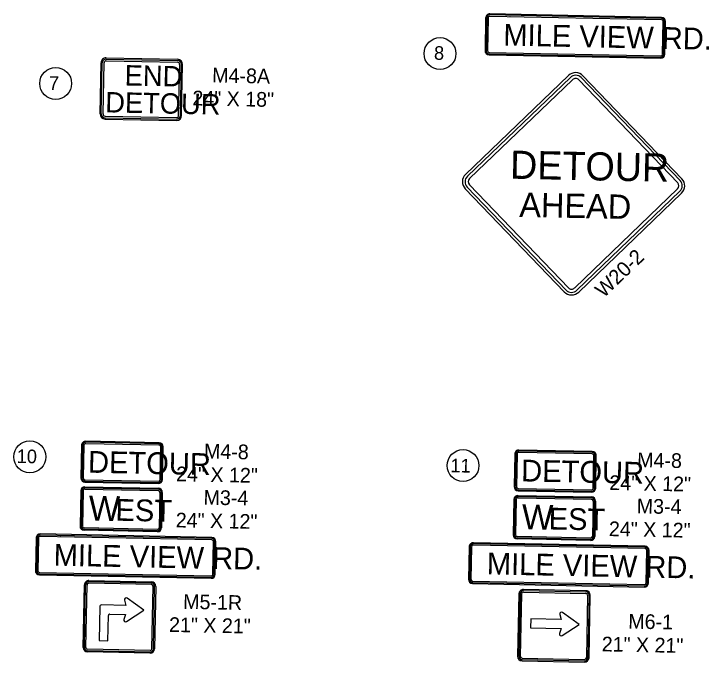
# Model space of a CAD drawing. Extents: x 299354 to 1325680, y 96128 to 228242.
# Drawn here: x 1320252 to 1322808, y 149023 to 151405 of the extents above; entities that cross this region are included whole.
import ezdxf

# ---------------------------------------------------------------- set-up
doc = ezdxf.new("R2010")
doc.units = 0
doc.layers.add('CA-TEXT', color=7, linetype='Continuous')
doc.layers.add('P_SGN_Cell', color=7, linetype='Continuous')

msp = doc.modelspace()

# ---------------------------------------------------------------- linework, layer by layer
at = {"layer": 'CA-TEXT'}
for centre in [(1321818.8, 151259.5), (1320405.8, 151149.7), (1320311, 149777), (1321903.4, 149745)]:
    msp.add_circle(centre, 58.6, dxfattribs=at)
at = {"layer": 'P_SGN_Cell'}
for p, q in [((1320591.9, 151243.8), (1320854.3, 151238.5)), ((1320569, 151038), (1320572.7, 151225.4)), ((1320573.7, 151037.9), (1320577.4, 151225.3)), ((1320579.9, 151037.8), (1320583.7, 151225.2)), ((1320591.7, 151232.9), (1320854.1, 151227.6)), ((1320591.8, 151239.1), (1320854.2, 151233.8)), ((1320858, 151032.2), (1320861.8, 151219.6)), ((1320864.2, 151032), (1320868, 151219.5)), ((1320868.9, 151031.9), (1320872.7, 151219.4)), ((1320587.3, 151018.9), (1320849.8, 151013.6)), ((1320587.4, 151023.5), (1320849.9, 151018.3)), ((1320587.6, 151029.8), (1320850, 151024.5)), ((1320513.1, 149667.2), (1320783.2, 149661.7)), ((1320513.1, 149658.4), (1320783, 149653)), ((1320513.2, 149663.4), (1320783.1, 149658)), ((1320498, 149652.5), (1320495.4, 149522.5)), ((1320501.7, 149652.4), (1320499.1, 149522.4)), ((1320506.7, 149652.3), (1320504.1, 149522.3)), ((1320789.2, 149646.6), (1320786.5, 149516.6)), ((1320794.2, 149646.5), (1320791.5, 149516.5)), ((1320797.9, 149646.4), (1320795.3, 149516.4)), ((1322105.5, 149635.1), (1322375.6, 149629.6)), ((1322105.6, 149631.3), (1322375.5, 149625.9)), ((1322090.4, 149620.4), (1322087.7, 149490.4)), ((1322094.1, 149620.3), (1322091.5, 149490.3)), ((1322099.1, 149620.2), (1322096.5, 149490.2)), ((1322105.5, 149626.3), (1322375.4, 149620.9)), ((1322381.5, 149614.5), (1322378.9, 149484.5)), ((1322386.5, 149614.4), (1322383.9, 149484.4)), ((1322390.3, 149614.3), (1322387.7, 149484.4)), ((1320780, 149501.7), (1320510, 149507.2)), ((1320780.1, 149505.5), (1320510.1, 149510.9)), ((1320780.2, 149510.5), (1320510.2, 149515.9)), ((1322372.4, 149473.4), (1322102.5, 149478.9)), ((1322372.6, 149478.4), (1322102.6, 149483.9)), ((1322372.4, 149469.7), (1322102.4, 149475.1)), ((1320506.9, 149076.5), (1320511.5, 149306.2)), ((1320511.3, 149076.4), (1320515.9, 149306.1)), ((1320516.8, 149076.3), (1320521.4, 149306)), ((1320757.7, 149307.8), (1320528.1, 149312.4)), ((1320757.8, 149313.2), (1320528.2, 149317.9)), ((1320528.3, 149322.2), (1320757.9, 149317.6)), ((1320759.5, 149071.4), (1320764.1, 149301.1)), ((1320765, 149071.3), (1320769.6, 149301)), ((1320774, 149300.9), (1320769.4, 149071.2)), ((1322108.8, 149273.5), (1322104.2, 149043.9)), ((1322113.2, 149273.4), (1322108.6, 149043.8)), ((1322118.6, 149273.3), (1322114, 149043.7)), ((1322125.3, 149279.7), (1322355, 149275.1)), ((1322355.2, 149285), (1322125.5, 149289.6)), ((1322125.5, 149285.2), (1322355.1, 149280.6)), ((1320658.4, 149249.9), (1320663.7, 149230.9)), ((1320729.5, 149213.2), (1320668.5, 149257)), ((1322361.4, 149268.4), (1322356.8, 149038.8)), ((1322366.9, 149268.3), (1322362.3, 149038.7)), ((1322366.6, 149038.6), (1322371.3, 149268.2)), ((1320567.9, 149226.3), (1320565.4, 149101.6)), ((1320663.7, 149230.9), (1320574.6, 149232.7)), ((1320605.6, 149199.2), (1320663, 149198.1)), ((1320663, 149198.1), (1320656.9, 149179.3)), ((1320666.8, 149171.8), (1320729.5, 149213.2)), ((1322259.3, 149197.9), (1322264.6, 149178.9)), ((1322330.4, 149161.1), (1322269.4, 149205)), ((1320598.2, 149100.9), (1320600.1, 149193.9)), ((1322152.5, 149181.1), (1322151.9, 149148.3)), ((1322264.6, 149178.9), (1322152.5, 149181.1)), ((1322151.9, 149148.3), (1322263.9, 149146.1)), ((1322263.9, 149146.1), (1322257.8, 149127.3)), ((1322267.7, 149119.8), (1322330.4, 149161.1)), ((1320565.4, 149101.6), (1320598.2, 149100.9)), ((1320752.8, 149065), (1320523.2, 149069.6)), ((1320752.6, 149055.2), (1320523, 149059.8)), ((1320752.7, 149059.5), (1320523.1, 149064.2)), ((1322120.3, 149031.5), (1322350, 149026.9)), ((1322120.3, 149027.1), (1322349.9, 149022.5)), ((1322120.5, 149037), (1322350.1, 149032.4))]:
    msp.add_line(p, q, dxfattribs=at)
for points in [[(1322633.1, 151383.7), (1322001.7, 151396.4)], [(1322633.2, 151388.7), (1322001.8, 151401.4)], [(1322633.3, 151392.5), (1322001.9, 151405.4)], [(1321986.6, 151390.5), (1321984.2, 151270.5)], [(1321990.4, 151390.4), (1321987.9, 151270.4)], [(1321995.4, 151390.3), (1321992.9, 151270.3)], [(1322636.8, 151257.4), (1322639.2, 151377.4)], [(1322641.8, 151257.3), (1322644.2, 151377.3)], [(1322645.6, 151257.2), (1322648, 151377.2)], [(1321998.9, 151255.2), (1322631, 151242.5)], [(1321999, 151259), (1322630.3, 151246.3)], [(1321999.1, 151264), (1322630.4, 151251.3)], [(1322291.3, 151179.1), (1321912.7, 150815.4)], [(1322297.9, 151172.2), (1321919.3, 150808.5)], [(1322701.2, 150792.8), (1322337.5, 151171.4)], [(1322708, 150799.4), (1322344.4, 151178)], [(1322306.2, 151163.6), (1321927.6, 150799.9)], [(1322692.6, 150784.5), (1322328.9, 151163.2)], [(1321911.6, 150762.4), (1322275.3, 150383.8)], [(1321918.5, 150769), (1322282.2, 150390.3)], [(1321927.1, 150777.2), (1322290.8, 150398.6)], [(1322313.8, 150398.4), (1322692.3, 150762)], [(1322322.1, 150389.8), (1322700.6, 150753.4)], [(1322328.7, 150383), (1322707.1, 150746.5)], [(1320501.1, 149819.6), (1320498.7, 149699.6)], [(1320504.8, 149819.5), (1320502.4, 149699.5)], [(1320509.8, 149819.4), (1320507.4, 149699.4)], [(1320786.2, 149820.1), (1320516.2, 149825.5)], [(1320786.3, 149825.1), (1320516.3, 149830.5)], [(1320786.3, 149828.9), (1320516.4, 149834.3)], [(1320789.9, 149693.8), (1320792.3, 149813.7)], [(1320794.9, 149693.7), (1320797.3, 149813.6)], [(1320798.6, 149693.6), (1320801, 149813.6)], [(1322093.5, 149787.5), (1322091.1, 149667.5)], [(1322097.2, 149787.4), (1322094.8, 149667.5)], [(1322102.2, 149787.3), (1322099.8, 149667.4)], [(1322378.5, 149788), (1322108.6, 149793.5)], [(1322378.6, 149793), (1322108.7, 149798.5)], [(1322378.7, 149796.8), (1322108.8, 149802.2)], [(1322382.2, 149661.7), (1322384.7, 149781.7)], [(1322387.2, 149661.6), (1322389.7, 149781.6)], [(1322391, 149661.5), (1322393.4, 149781.5)], [(1320513.4, 149684.3), (1320783.3, 149678.9)], [(1320513.5, 149688.1), (1320783.4, 149682.6)], [(1320513.6, 149693.1), (1320783.5, 149687.6)], [(1322105.9, 149661), (1322375.9, 149655.6)], [(1322105.8, 149656), (1322375.8, 149650.6)], [(1322105.8, 149652.2), (1322375.7, 149646.8)], [(1320333.6, 149478.6), (1320331.2, 149358.6)], [(1320337.4, 149478.5), (1320335, 149358.6)], [(1320342.4, 149478.4), (1320340, 149358.5)], [(1320980.1, 149471.8), (1320348.8, 149484.6)], [(1320980.3, 149480.6), (1320348.9, 149493.5)], [(1320980.2, 149476.8), (1320348.9, 149489.6)], [(1320983.8, 149345.5), (1320986.2, 149465.5)], [(1320988.8, 149345.4), (1320991.2, 149465.4)], [(1320992.6, 149345.3), (1320995, 149465.3)], [(1322572.5, 149439.8), (1321941.1, 149452.5)], [(1322572.6, 149444.8), (1321941.2, 149457.5)], [(1322572.7, 149448.5), (1321941.3, 149461.4)], [(1321926, 149446.5), (1321923.6, 149326.6)], [(1321929.8, 149446.5), (1321927.4, 149326.5)], [(1321934.8, 149446.4), (1321932.4, 149326.4)], [(1322576.2, 149313.4), (1322578.6, 149433.4)], [(1322581.2, 149313.3), (1322583.6, 149433.3)], [(1322585, 149313.2), (1322587.4, 149433.2)], [(1320346.1, 149352.1), (1320977.5, 149339.4)], [(1320345.9, 149343.3), (1320978, 149330.6)], [(1320346, 149347.1), (1320977.4, 149334.4)], [(1321938.3, 149311.3), (1322570.4, 149298.5)], [(1321938.4, 149315), (1322569.7, 149302.3)], [(1321938.5, 149320), (1322569.8, 149307.3)]]:
    msp.add_lwpolyline(points, dxfattribs=at)
for centre, radius, start, end in [((1322001.6, 151390.4), 15, 88.8468, 178.8468), ((1322001.6, 151390.2), 11.2, 88.8468, 178.8468), ((1322001.6, 151390.2), 6.25, 88.8468, 178.8468), ((1322076, 151388.7), 6.25, 88.8468, 96.1883), ((1322633, 151377.5), 6.25, 358.8468, 88.8468), ((1322633, 151377.5), 11.2, 358.8468, 88.8468), ((1322633, 151377.5), 15, 358.8468, 88.8468), ((1321999.2, 151270.2), 15, 178.8468, 268.8468), ((1321999.2, 151270.2), 11.2, 178.8468, 268.8468), ((1321999.2, 151270.2), 6.25, 178.8468, 268.8468), ((1320591.5, 151225.1), 18.7, 88.8468, 178.8468), ((1322630.6, 151257.5), 11.2, 268.8468, 358.8468), ((1322630.6, 151257.5), 15, 268.8468, 358.8468), ((1322630.6, 151257.5), 6.25, 268.8468, 358.8468), ((1320591.5, 151225.1), 14.1, 88.8468, 178.8468), ((1320591.5, 151225.1), 7.81, 88.8468, 178.8468), ((1320591.5, 151225.1), 7.81, 88.8468, 97.6911), ((1320853.9, 151219.8), 7.81, 358.8468, 88.8468), ((1320853.9, 151219.8), 14.1, 358.8468, 88.8468), ((1320853.9, 151219.8), 18.7, 358.8468, 88.8468), ((1322317.3, 151152), 37.5, 43.8449, 133.8468), ((1322317.3, 151152), 28, 43.8449, 133.8468), ((1322317.3, 151152), 16.1, 43.8449, 133.8468), ((1320587.7, 151037.6), 18.7, 178.8468, 268.8468), ((1320587.7, 151037.6), 14.1, 178.8468, 268.8468), ((1320587.7, 151037.6), 7.81, 178.8468, 268.8468), ((1320850.2, 151032.3), 18.7, 268.8468, 358.8468), ((1320850.2, 151032.3), 14.1, 268.8468, 358.8468), ((1320850.2, 151032.3), 7.81, 268.8468, 358.8468), ((1321938.7, 150788.4), 37.5, 133.8468, 223.8468), ((1321938.7, 150788.4), 28, 133.8468, 223.8468), ((1321938.7, 150788.4), 16.1, 133.8468, 223.8468), ((1322681, 150773.4), 16.1, 313.8468, 43.8468), ((1322681, 150773.4), 28, 313.8468, 43.8468), ((1322681, 150773.4), 37.5, 313.8468, 43.8468), ((1322302.4, 150409.7), 16.1, 223.854, 314.4977), ((1322302.4, 150409.7), 37.5, 223.854, 314.4977), ((1322302.4, 150409.7), 28, 223.854, 314.4977), ((1320516.1, 149819.3), 15, 88.8468, 178.8468), ((1320516.1, 149819.3), 11.2, 88.8468, 178.8468), ((1320516.1, 149819.3), 6.25, 88.8468, 178.8468), ((1320516.1, 149819.3), 6.25, 88.8468, 96.1883), ((1320786, 149813.9), 6.25, 358.8468, 88.8468), ((1320786, 149813.9), 15, 358.8468, 88.8468), ((1320786, 149813.9), 11.2, 358.8468, 88.8468), ((1322108.5, 149787.2), 15, 88.8468, 178.8468), ((1322108.5, 149787.2), 11.2, 88.8468, 178.8468), ((1322108.5, 149787.2), 6.25, 88.8468, 178.8468), ((1322108.5, 149787.2), 6.25, 88.8468, 96.1883), ((1322378.4, 149781.8), 6.25, 358.8468, 88.8468), ((1322378.4, 149781.8), 11.2, 358.8468, 88.8468), ((1322378.4, 149781.8), 15, 358.8468, 88.8468), ((1320513.7, 149699.3), 15, 178.8468, 268.8468), ((1320513.7, 149699.3), 11.2, 178.8468, 268.8468), ((1320513.7, 149699.3), 6.25, 178.8468, 268.8468), ((1320783.6, 149693.9), 15, 268.8468, 358.8468), ((1320783.6, 149693.9), 11.2, 268.8468, 358.8468), ((1320783.6, 149693.9), 6.25, 268.8468, 358.8468), ((1320513, 149652.2), 15, 89.6119, 178.8462), ((1320513, 149652.2), 11.2, 88.8462, 178.8462), ((1320513, 149652.2), 6.25, 88.8462, 178.8462), ((1320782.9, 149646.7), 11.2, 358.8462, 88.8462), ((1320782.9, 149646.7), 15, 358.8462, 88.8462), ((1322106.1, 149667.2), 15, 178.8468, 268.8468), ((1322106.1, 149667.2), 11.2, 178.8468, 268.8468), ((1322106.1, 149667.2), 6.25, 178.8468, 268.8468), ((1322376, 149661.8), 15, 268.8468, 358.8468), ((1322376, 149661.8), 11.2, 268.8468, 358.8468), ((1322376, 149661.8), 6.25, 268.8468, 358.8468), ((1320782.9, 149646.7), 6.25, 358.8462, 88.8462), ((1322105.3, 149620.1), 15, 89.6119, 178.8462), ((1322105.3, 149620.1), 11.2, 88.8462, 178.8462), ((1322105.3, 149620.1), 6.25, 88.8462, 178.8462), ((1322375.3, 149614.6), 6.25, 358.8462, 88.8462), ((1322375.3, 149614.6), 11.2, 358.8462, 88.8462), ((1322375.3, 149614.6), 15, 358.8462, 88.8462), ((1320510.4, 149522.2), 15, 178.8462, 268.8462), ((1320510.4, 149522.2), 11.2, 178.8462, 268.8462), ((1320510.4, 149522.2), 6.25, 178.8462, 268.8462), ((1320780.3, 149516.7), 15, 268.8462, 358.8462), ((1320780.3, 149516.7), 11.2, 268.8462, 358.8462), ((1320780.3, 149516.7), 6.25, 268.8462, 358.8462), ((1320348.6, 149478.5), 15, 88.8468, 178.8468), ((1320348.6, 149478.3), 11.2, 88.8468, 178.8468), ((1320348.6, 149478.3), 6.25, 88.8468, 178.8468), ((1320423.1, 149476.8), 6.25, 88.8468, 96.1883), ((1320980, 149465.6), 15, 358.8468, 88.8468), ((1322102.7, 149490.1), 15, 178.8462, 268.8462), ((1322102.7, 149490.1), 11.2, 178.8462, 268.8462), ((1322102.7, 149490.1), 6.25, 178.8462, 268.8462), ((1322372.7, 149484.7), 11.2, 268.8462, 358.8462), ((1322372.7, 149484.7), 15, 268.8462, 358.8462), ((1322372.7, 149484.7), 6.25, 268.8462, 358.8462), ((1320980, 149465.6), 6.25, 358.8468, 88.8468), ((1320980, 149465.6), 11.2, 358.8468, 88.8468), ((1321941, 149446.4), 15, 88.8468, 178.8468), ((1321941, 149446.2), 11.2, 88.8468, 178.8468), ((1321941, 149446.2), 6.25, 88.8468, 178.8468), ((1322015.5, 149444.7), 6.25, 88.8468, 96.1883), ((1322572.4, 149433.5), 6.25, 358.8468, 88.8468), ((1322572.4, 149433.5), 11.2, 358.8468, 88.8468), ((1322572.4, 149433.5), 15, 358.8468, 88.8468), ((1320346.2, 149358.3), 15, 178.8468, 268.8468), ((1320346.2, 149358.3), 11.2, 178.8468, 268.8468), ((1320346.2, 149358.3), 6.25, 178.8468, 268.8468), ((1320977.6, 149345.6), 15, 268.8468, 358.8468), ((1320977.6, 149345.6), 11.2, 268.8468, 358.8468), ((1320977.6, 149345.6), 6.25, 268.8468, 358.8468), ((1321938.6, 149326.3), 15, 178.8468, 268.8468), ((1321938.6, 149326.3), 11.2, 178.8468, 268.8468), ((1321938.6, 149326.3), 6.25, 178.8468, 268.8468), ((1320527.9, 149305.8), 16.4, 88.8462, 178.8462), ((1320527.9, 149305.8), 12, 88.8462, 178.8462), ((1320527.9, 149305.8), 6.56, 88.8462, 178.8462), ((1320757.6, 149301.2), 6.56, 358.8462, 88.8462), ((1320757.6, 149301.2), 12, 358.8462, 88.8462), ((1320757.6, 149301.2), 16.4, 358.8462, 88.8462), ((1322570, 149313.6), 15, 268.8468, 358.8468), ((1322570, 149313.6), 11.2, 268.8468, 358.8468), ((1322570, 149313.6), 6.25, 268.8468, 358.8468), ((1322125.2, 149273.2), 16.4, 88.8468, 178.8468), ((1322125.2, 149273.2), 12, 88.8468, 178.8468), ((1322125.2, 149273.2), 6.56, 88.8468, 178.8468), ((1322354.9, 149268.6), 6.56, 358.8468, 88.8468), ((1322354.9, 149268.6), 12, 358.8468, 88.8468), ((1322354.9, 149268.6), 16.4, 59.4503, 88.8468), ((1322354.9, 149268.6), 16.4, 358.8468, 88.8468), ((1320664.7, 149251.7), 6.56, 54.3166, 195.6488), ((1320574.5, 149226.1), 6.56, 88.8462, 178.8462), ((1320605.5, 149193.8), 5.47, 88.8462, 178.8462), ((1322265.6, 149199.7), 6.56, 54.3172, 195.6494), ((1320663.2, 149177.3), 6.56, 162.0436, 303.3759), ((1322264.1, 149125.3), 6.56, 162.0442, 303.3765), ((1320523.3, 149076.2), 16.4, 178.8462, 268.8462), ((1320523.3, 149076.2), 12, 178.8462, 268.8462), ((1320523.3, 149076.2), 6.56, 178.8462, 268.8462), ((1320753, 149071.6), 16.4, 268.8462, 358.8462), ((1320753, 149071.6), 12, 268.8462, 358.8462), ((1320753, 149071.6), 6.56, 268.8462, 358.8462), ((1322120.6, 149043.5), 16.4, 178.8468, 268.8468), ((1322120.6, 149043.5), 12, 178.8468, 268.8468), ((1322120.6, 149043.5), 6.56, 178.8468, 268.8468), ((1322350.2, 149038.9), 16.4, 268.8468, 358.8468), ((1322350.2, 149038.9), 12, 268.8468, 358.8468), ((1322350.2, 149038.9), 6.56, 268.8468, 358.8468)]:
    msp.add_arc(centre, radius, start, end, dxfattribs=at)

# ---------------------------------------------------------------- texts
at = {"layer": 'CA-TEXT'}
for s, p in [('8', (1321796.3, 151237)), ('7', (1320380.6, 151126.4)), ('10', (1320262.3, 149754.7)), ('11', (1321856.7, 149720.5))]:
    msp.add_text(s, height=50, rotation=358.8468, dxfattribs=at).set_placement(p)
at = {"layer": 'P_SGN_Cell'}
for s, height, rotation, p in [('MILE VIEW RD.', 80, 358.8468, (1322050.9, 151289)), ('END', 75, 358.8468, (1320659, 151142.4)), ('M4-8A', 54, 358.8468, (1320980.8, 151153.5)), ('DETOUR', 75, 358.8468, (1320587.6, 151043.5)), ('24" X 18"', 54, 358.8468, (1320908, 151069.3)), ('DETOUR', 103.57, 358.8468, (1322075.6, 150799.7)), ('AHEAD', 89.29, 358.8468, (1322109.6, 150659.4)), ('W20-2', 54, 43.8468, (1322420.5, 150359.2)), ('M4-8', 54, 358.8468, (1320950.7, 149771.2)), ('DETOUR', 80, 358.8468, (1320524.2, 149718.9)), ('M4-8', 54, 358.8468, (1322543.1, 149739.1)), ('DETOUR', 80, 358.8468, (1322116.5, 149686.9)), ('24" X 12"', 54, 358.8468, (1320848.4, 149687.5)), ('24" X 12"', 54, 358.8468, (1322440.8, 149655.4)), ('W', 91.4, 358.8462, (1320526.5, 149543.3)), ('M3-4', 54, 358.8462, (1320949.1, 149601.5)), ('EST', 80, 358.8462, (1320625.1, 149542.4)), ('M3-4', 54, 358.8462, (1322541.5, 149569.5)), ('W', 91.4, 358.8462, (1322118.9, 149511.2)), ('EST', 80, 358.8462, (1322217.5, 149510.3)), ('24" X 12"', 54, 358.8462, (1320846.8, 149517.9)), ('24" X 12"', 54, 358.8462, (1322439.2, 149485.8)), ('MILE VIEW RD.', 80, 358.8468, (1320397.9, 149377.1)), ('MILE VIEW RD.', 80, 358.8468, (1321990.3, 149345)), ('M5-1R', 54, 358.8462, (1320874.1, 149218.3)), ('M6-1', 54, 358.8468, (1322510.4, 149145.8)), ('21" X 21"', 54, 358.8462, (1320822.3, 149133.6)), ('21" X 21"', 54, 358.8468, (1322412.8, 149062.1))]:
    msp.add_text(s, height=height, rotation=rotation, dxfattribs=at).set_placement(p)

doc.saveas('drawing.dxf')
